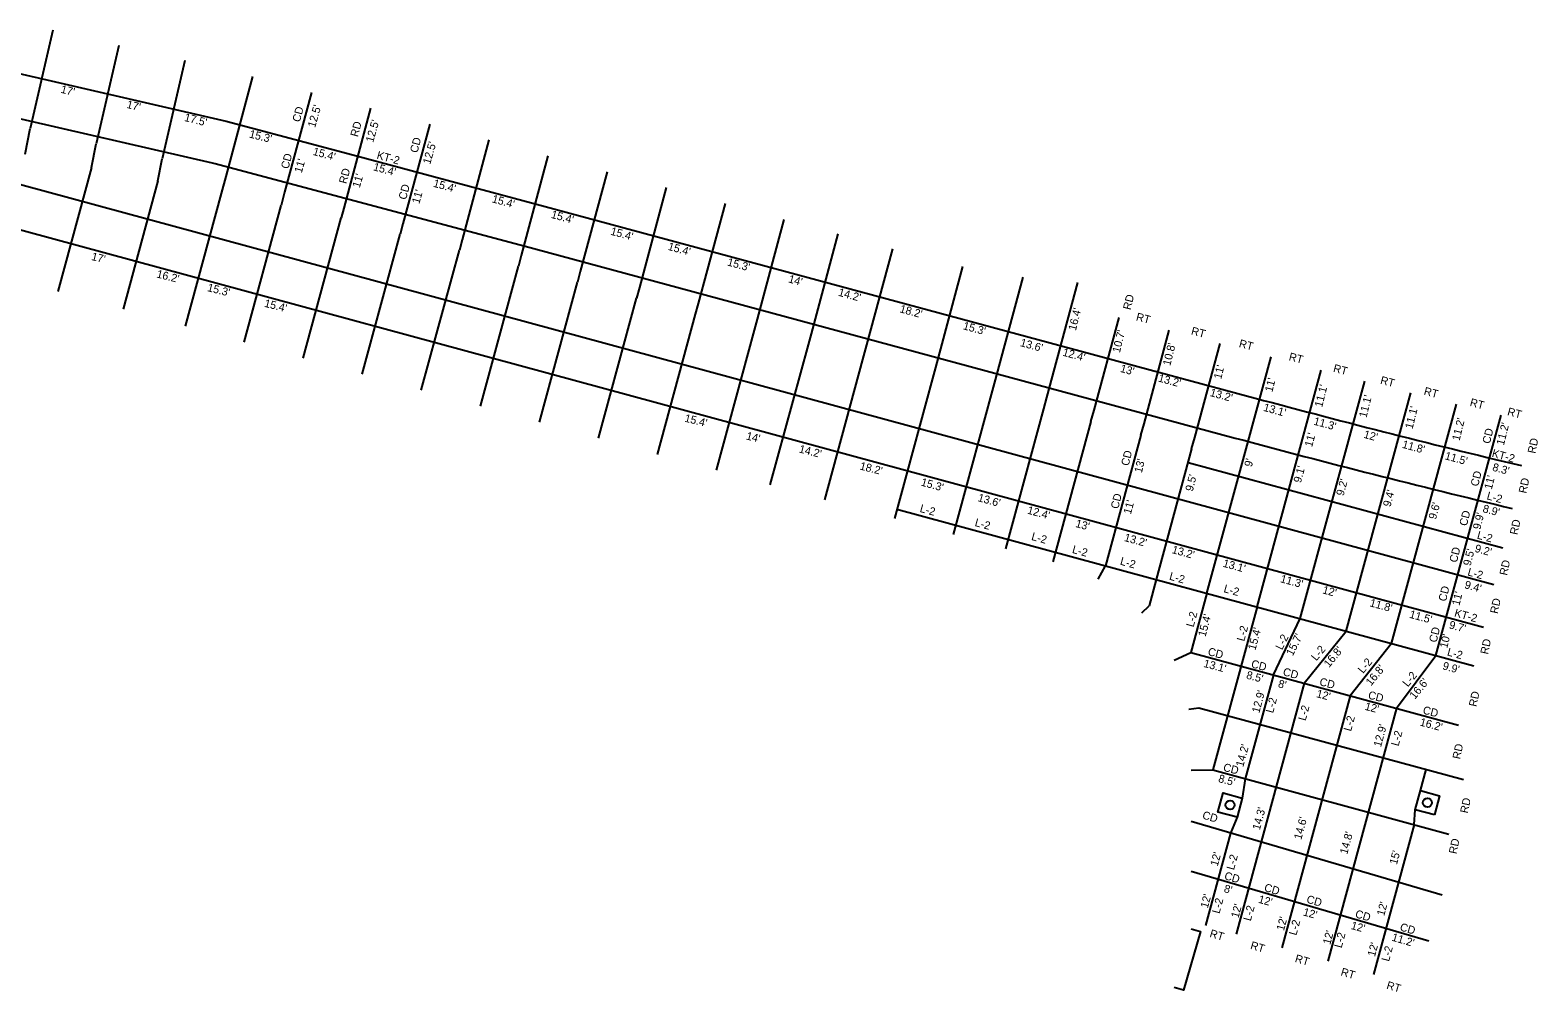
# Model space of a CAD drawing. Extents: x 4995357 to 4999033, y 3881202 to 3881750.
# Drawn here: x 4998653.9 to 4999033, y 3881202.4 to 3881444.2 of the extents above; entities that cross this region are included whole.
import ezdxf

# ---------------------------------------------------------------- set-up
doc = ezdxf.new("R2010")
doc.units = 0
for name, color, linetype in [('dsn3DCenterLine', 7, 'Continuous'), ('dsn3DCurbFormgrade', 7, 'Continuous'), ('dsn3DCurbTop', 7, 'Continuous'), ('dsn3DDitchFront', 7, 'Continuous'), ('dsn3DDNC', 7, 'Continuous'), ('dsn3DExistingPvmtBtm', 7, 'Continuous')]:
    doc.layers.add(name, color=color, linetype=linetype)

msp = doc.modelspace()

# ---------------------------------------------------------------- linework, layer by layer
at = {"layer": 'dsn3DCurbFormgrade'}
for p, q in [((4998659.59, 3881444.17), (4998653.9, 3881419.44)), ((4998676.2, 3881440.35), (4998670.51, 3881415.62)), ((4998692.81, 3881436.53), (4998687.12, 3881411.8)), ((4998709.81, 3881432.48), (4998703.09, 3881407.37)), ((4998724.61, 3881428.52), (4998717.89, 3881403.41)), ((4998739.5, 3881424.54), (4998732.78, 3881399.43)), ((4998754.36, 3881420.57), (4998747.64, 3881395.45)), ((4998769.22, 3881416.59), (4998762.5, 3881391.47)), ((4998784.09, 3881412.61), (4998777.37, 3881387.5)), ((4998669.31, 3881409.65), (4998660.85, 3881378.49)), ((4998799, 3881408.59), (4998792.22, 3881383.49)), ((4998686.01, 3881406.29), (4998677.25, 3881374.03)), ((4998813.85, 3881404.58), (4998807.08, 3881379.48)), ((4998701.95, 3881403.08), (4998692.9, 3881369.78)), ((4998821.94, 3881375.47), (4998828.72, 3881400.57)), ((4998707.68, 3881365.77), (4998717, 3881400.05)), ((4998722.55, 3881361.73), (4998732.12, 3881396.95)), ((4998836.75, 3881371.47), (4998843.52, 3881396.57)), ((4998737.4, 3881357.7), (4998746.96, 3881392.92)), ((4998857.01, 3881392.93), (4998850.24, 3881367.83)), ((4998752.25, 3881353.66), (4998761.81, 3881388.89)), ((4998870.74, 3881389.23), (4998863.96, 3881364.13)), ((4998767.09, 3881349.63), (4998776.66, 3881384.85)), ((4998888.36, 3881384.75), (4998881.52, 3881359.38)), ((4998903.53, 3881382.09), (4998896.3, 3881355.32)), ((4998781.94, 3881345.6), (4998791.51, 3881380.82)), ((4998917.24, 3881380.72), (4998909.45, 3881351.84)), ((4998796.79, 3881341.57), (4998806.35, 3881376.79)), ((4998811.64, 3881337.53), (4998821.2, 3881372.76)), ((4998921.4, 3881348.62), (4998927.7, 3881371.95)), ((4998826.44, 3881333.51), (4998836, 3881368.74)), ((4998933.96, 3881345.22), (4998940.3, 3881368.72)), ((4998849.49, 3881365.08), (4998839.92, 3881329.85)), ((4998946.72, 3881341.78), (4998953.1, 3881365.41)), ((4998863.21, 3881361.35), (4998853.64, 3881326.13)), ((4998960.14, 3881340.74), (4998965.89, 3881362.03)), ((4998962.4, 3881299.18), (4998978.52, 3881358.69)), ((4998880.76, 3881356.58), (4998871.19, 3881321.36)), ((4998973.26, 3881296.23), (4998989.46, 3881355.9)), ((4998895.55, 3881352.57), (4998885.99, 3881317.34)), ((4998984.81, 3881293.09), (4999001.07, 3881352.95)), ((4998908.68, 3881349), (4998899.11, 3881313.78)), ((4998996.21, 3881290), (4999012.55, 3881350.14)), ((4999007.31, 3881286.98), (4999023.72, 3881347.41)), ((4998920.62, 3881345.76), (4998911.06, 3881310.53)), ((4998933.18, 3881342.35), (4998924.27, 3881309.54)), ((4998949.79, 3881302.61), (4998960.14, 3881340.74)), ((4998945.94, 3881338.88), (4998937.03, 3881306.07)), ((4998922.41, 3881306.15), (4998924.27, 3881309.54)), ((4998933.4, 3881297.68), (4998935.22, 3881299.41)), ((4998966.52, 3881282.08), (4998973.26, 3881296.23)), ((4998974.24, 3881279.99), (4998984.81, 3881293.09)), ((4998941.54, 3881285.76), (4998945.75, 3881287.72)), ((4998945.75, 3881287.72), (4999012.99, 3881269.46)), ((4998996.21, 3881290), (4998985.82, 3881276.84)), ((4998997.4, 3881273.7), (4999007.31, 3881286.98)), ((4998945.26, 3881273.46), (4998947.73, 3881273.83)), ((4998947.73, 3881273.83), (4999014.27, 3881255.76)), ((4998945.79, 3881258.17), (4998951.28, 3881258.18)), ((4998951.28, 3881258.18), (4999010.56, 3881242.08)), ((4999008.92, 3881226.7), (4998945.79, 3881245.19)), ((4999005.54, 3881215.18), (4998945.82, 3881232.68))]:
    msp.add_line(p, q, dxfattribs=at)
msp.add_arc((4999585.3, 3883669.29), 2411, 254.89079, 256.59997, dxfattribs=at)
at = {"layer": 'dsn3DCurbTop'}
for p, q in [((4998652.61, 3881413.01), (4998653.9, 3881419.44)), ((4998669.31, 3881409.65), (4998670.51, 3881415.62)), ((4998686.01, 3881406.29), (4998687.12, 3881411.8)), ((4998703.09, 3881407.37), (4998701.95, 3881403.08)), ((4998717.89, 3881403.41), (4998717, 3881400.05)), ((4998732.78, 3881399.43), (4998732.12, 3881396.95)), ((4998747.64, 3881395.45), (4998746.96, 3881392.92)), ((4998762.5, 3881391.47), (4998761.81, 3881388.89)), ((4998777.37, 3881387.5), (4998776.66, 3881384.85)), ((4998792.22, 3881383.49), (4998791.51, 3881380.82)), ((4998807.08, 3881379.48), (4998806.35, 3881376.79)), ((4998821.2, 3881372.76), (4998821.94, 3881375.47)), ((4998836, 3881368.74), (4998836.75, 3881371.47)), ((4998850.24, 3881367.83), (4998849.49, 3881365.08)), ((4998863.96, 3881364.1), (4998863.21, 3881361.35)), ((4998881.5, 3881359.34), (4998880.76, 3881356.58)), ((4998896.3, 3881355.32), (4998895.55, 3881352.57)), ((4998909.45, 3881351.84), (4998908.68, 3881349)), ((4998920.62, 3881345.76), (4998921.4, 3881348.62)), ((4998933.18, 3881342.35), (4998933.96, 3881345.22)), ((4998945.94, 3881338.88), (4998946.72, 3881341.76))]:
    msp.add_line(p, q, dxfattribs=at)
at = {"layer": 'dsn3DDitchFront'}
for p, q in [((4998736.27, 3881412.47), (4998783.36, 3881399.87)), ((4998614.91, 3881403.91), (4999019.28, 3881294.09)), ((4998783.36, 3881399.87), (4998959.72, 3881352.25))]:
    msp.add_line(p, q, dxfattribs=at)
msp.add_arc((4999585.3, 3883669.29), 2400, 254.89079, 256.59429, dxfattribs=at)
at = {"layer": 'dsn3DDNC'}
for p, q in [((4998630.07, 3881438.13), (4998703.22, 3881421.31)), ((4998627.39, 3881427.46), (4998700.75, 3881410.59)), ((4998703.22, 3881421.31), (4998736.27, 3881412.47)), ((4998614.25, 3881415.49), (4999021.9, 3881304.78)), ((4998700.38, 3881410.68), (4998780.52, 3881389.24)), ((4998780.5, 3881389.25), (4998956.85, 3881341.63)), ((4998945.02, 3881335.5), (4999024.16, 3881314.01)), ((4998871.84, 3881323.77), (4999016.9, 3881284.38)), ((4998937.03, 3881306.07), (4998935.22, 3881299.41)), ((4998949.79, 3881302.61), (4998945.75, 3881287.73)), ((4998962.4, 3881299.18), (4998951.28, 3881258.18)), ((4998974.24, 3881279.99), (4998957.1, 3881216.87)), ((4998966.52, 3881282.08), (4998959.43, 3881255.97)), ((4998985.82, 3881276.84), (4998968.62, 3881213.5)), ((4998997.4, 3881273.7), (4998980.14, 3881210.12)), ((4999003.47, 3881253.02), (4999004.9, 3881258.3)), ((4998959.43, 3881255.97), (4998958.67, 3881251.12)), ((4998957.36, 3881246.29), (4998955.71, 3881242.29)), ((4999001.89, 3881244.43), (4999002.16, 3881248.19)), ((4998955.71, 3881242.29), (4998949.42, 3881219.12)), ((4999001.89, 3881244.43), (4998991.66, 3881206.75))]:
    msp.add_line(p, q, dxfattribs=at)
at = {"layer": 'dsn3DExistingPvmtBtm'}
for points in [[(4998957.36, 3881246.29), (4998952.53, 3881247.6), (4998953.84, 3881252.43), (4998958.67, 3881251.12)], [(4999006.98, 3881246.88), (4999002.16, 3881248.19), (4999003.47, 3881253.02), (4999008.29, 3881251.71)]]:
    msp.add_lwpolyline(points, close=True, dxfattribs=at)
msp.add_lwpolyline([(4998945.79, 3881218.24), (4998948.19, 3881217.54), (4998943.9, 3881202.82), (4998941.5, 3881203.52)], dxfattribs=at)
for centre in [(4998955.6, 3881249.36), (4999005.22, 3881249.95)]:
    msp.add_circle(centre, 1.12, dxfattribs=at)

# ---------------------------------------------------------------- texts
at = {"layer": 'dsn3DCenterLine'}
for s, rotation, p in [("17'", 345.9626, (4998661.46, 3881428.46)), ("17'", 345.9626, (4998678.01, 3881424.65)), ("17.5'", 345.9626, (4998692.53, 3881421.36)), ('CD', 75.0269, (4998721.7, 3881420.92)), ("12.5'", 73.8704, (4998725.54, 3881419.53)), ('RD', 75.0269, (4998736.29, 3881417.2)), ("12.5'", 73.8704, (4998740.13, 3881415.8)), ("15.3'", 345.9626, (4998708.84, 3881417.21)), ('CD', 75.0269, (4998751.27, 3881413.18)), ("12.5'", 73.8704, (4998754.48, 3881410.31)), ('CD', 75.0269, (4998718.83, 3881409.14)), ("11'", 73.8704, (4998722.17, 3881408.12)), ("15.4'", 344.7365, (4998724.84, 3881412.84)), ('KT-2', 344.7365, (4998740.9, 3881411.89)), ('RD', 75.0269, (4998733.42, 3881405.41)), ("11'", 73.8704, (4998736.76, 3881404.39)), ("15.4'", 344.7365, (4998740.02, 3881408.98)), ('CD', 75.0269, (4998748.4, 3881401.4)), ("11'", 73.8704, (4998751.74, 3881400.38)), ("15.4'", 344.7365, (4998755.1, 3881404.83)), ("15.4'", 344.7365, (4998769.88, 3881400.91)), ("15.4'", 344.7365, (4998784.73, 3881397)), ("15.4'", 344.7365, (4998799.68, 3881392.78)), ("15.4'", 344.7365, (4998814.11, 3881388.96)), ("17'", 345.9626, (4998669.16, 3881386.41)), ("15.3'", 344.7365, (4998829.04, 3881385.04)), ("16.2'", 345.9626, (4998685.54, 3881382.02)), ("14'", 344.7365, (4998844.4, 3881380.79)), ("15.3'", 345.9626, (4998698.31, 3881378.59)), ("14.2'", 344.7365, (4998856.94, 3881377.43)), ('RD', 75.9626, (4998930.57, 3881373.71)), ("15.4'", 345.9626, (4998712.63, 3881374.65)), ("18.2'", 344.7365, (4998872.39, 3881373.27)), ("16.4'", 75.9626, (4998916.82, 3881368.49)), ("15.3'", 344.7365, (4998888.31, 3881369)), ('RT', 345.4164, (4998931.82, 3881371.24)), ("13.6'", 344.7365, (4998902.68, 3881364.77)), ("10.7'", 75.9626, (4998927.88, 3881362.92)), ('RT', 345.4164, (4998945.67, 3881367.69)), ('RT', 345.4164, (4998957.69, 3881364.54)), ("12.4'", 344.7365, (4998913.35, 3881362.37)), ("10.8'", 75.9626, (4998940.56, 3881359.67)), ('RT', 345.4164, (4998970.23, 3881361.22)), ("13'", 344.7365, (4998927.83, 3881358.29)), ("11'", 75.9626, (4998953.36, 3881356.3)), ('RT', 345.4164, (4998981.39, 3881358.31)), ("13.2'", 344.7365, (4998937.38, 3881355.88)), ("11'", 75.9626, (4998966.23, 3881353.05)), ("11.1'", 75.9626, (4998978.74, 3881349.23)), ('RT', 345.4164, (4998993.23, 3881355.3)), ("13.2'", 344.7365, (4998950.39, 3881352.22)), ("11.1'", 75.9626, (4998989.89, 3881346.6)), ('RT', 345.4164, (4999004.18, 3881352.56)), ('RT', 345.4164, (4999015.75, 3881349.73)), ("15.4'", 345.9626, (4998818.3, 3881345.78)), ("13.1'", 344.7365, (4998963.83, 3881348.49)), ("11.1'", 75.9626, (4999001.47, 3881343.76)), ('RT', 345.4164, (4999025.17, 3881347.42)), ("11.3'", 344.7365, (4998976.45, 3881345.03)), ("12'", 344.7365, (4998989.04, 3881341.72)), ("11.2'", 75.9626, (4999013.28, 3881340.81)), ('CD', 75.9626, (4999020.91, 3881340.05)), ("11.2'", 75.9626, (4999024.44, 3881339.66)), ("14'", 345.9626, (4998833.78, 3881341.3)), ("14.2'", 345.9626, (4998847.06, 3881338.02)), ("11'", 74.8061, (4998976.21, 3881339.24)), ("11.8'", 344.7365, (4998998.72, 3881339.21)), ('RD', 77.9434, (4999032.33, 3881337.61)), ('CD', 75.9626, (4998930.08, 3881334.49)), ("13'", 75.9626, (4998933.4, 3881332.72)), ("9'", 74.8061, (4998961.03, 3881334.21)), ("11.5'", 344.7365, (4999009.46, 3881336.32)), ('KT-2', 344.7365, (4999021.28, 3881336.95)), ("18.2'", 345.9626, (4998862.36, 3881333.74)), ("9.5'", 75.9626, (4998946.22, 3881328.08)), ("9.1'", 74.8061, (4998973.4, 3881330.22)), ('CD', 75.9626, (4999017.96, 3881329.33)), ("11'", 75.9626, (4999021.38, 3881328.56)), ("8.3'", 344.7365, (4999021.41, 3881333.46)), ("15.3'", 344.7365, (4998877.73, 3881329.7)), ("9.2'", 74.8061, (4998984.13, 3881326.95)), ("9.4'", 74.8061, (4998995.91, 3881324.19)), ('RD', 77.9434, (4999030.07, 3881327.59)), ('L-2', 344.7349, (4998877.45, 3881323.08)), ("13.6'", 344.7365, (4998892.03, 3881325.79)), ("12.4'", 344.7365, (4998904.46, 3881322.66)), ('CD', 75.9626, (4998927.47, 3881323.67)), ("11'", 74.8061, (4998930.65, 3881322.33)), ("9.6'", 74.8061, (4999007.36, 3881321.03)), ("8.9'", 344.7365, (4999018.97, 3881323.04)), ('L-2', 344.7349, (4999019.99, 3881326.26)), ('L-2', 344.7349, (4998891.27, 3881319.55)), ("13'", 344.7365, (4998916.59, 3881319.3)), ('CD', 75.9626, (4999015.12, 3881319.38)), ("9.9'", 75.9626, (4999018.52, 3881318.48)), ('RD', 77.9434, (4999027.85, 3881317.17)), ('L-2', 344.7349, (4998905.49, 3881316.04)), ("13.2'", 344.7365, (4998928.83, 3881315.77)), ('L-2', 344.7349, (4999017.55, 3881316.38)), ('L-2', 344.7349, (4998915.75, 3881312.78)), ("13.2'", 344.7365, (4998940.82, 3881312.73)), ('CD', 75.9626, (4999012.61, 3881310.19)), ("9.5'", 75.9626, (4999016.08, 3881309.36)), ("9.2'", 344.7365, (4999016.98, 3881313.04)), ('L-2', 344.7349, (4998927.81, 3881309.83)), ("13.1'", 344.7365, (4998953.65, 3881309.3)), ('RD', 77.9434, (4999025.24, 3881306.96)), ('L-2', 344.7349, (4998940.17, 3881306.05)), ("11.3'", 344.7365, (4998968.09, 3881305.41)), ("9.4'", 344.7365, (4999014.41, 3881303.91)), ('L-2', 344.7349, (4999015.17, 3881307.13)), ('L-2', 344.7349, (4998953.84, 3881302.91)), ("12'", 344.7365, (4998978.69, 3881302.61)), ('CD', 75.9626, (4999009.87, 3881300.41)), ("11'", 75.9626, (4999013.25, 3881299.37)), ('L-2', 74.8061, (4998946.41, 3881293.96)), ("11.8'", 344.7365, (4998990.56, 3881299.36)), ("11.5'", 344.7365, (4999000.54, 3881296.48)), ('KT-2', 344.4604, (4999011.84, 3881296.82)), ('RD', 77.9434, (4999022.88, 3881297.34)), ("15.4'", 74.8061, (4998949.41, 3881291.53)), ('L-2', 74.8061, (4998959.15, 3881290.4)), ("15.4'", 74.8061, (4998961.96, 3881288.15)), ('CD', 75.9626, (4999007.5, 3881290.09)), ("9.7'", 344.7365, (4999010.5, 3881293.82)), ('L-2', 63.6883, (4998968.67, 3881288.2)), ("15.7'", 63.6883, (4998971.36, 3881286.7)), ("10'", 75.9626, (4999010.18, 3881288.66)), ('RD', 77.9434, (4999020.44, 3881287.13)), ('CD', 345.1995, (4998949.86, 3881287.09)), ('L-2', 50.4873, (4998977.28, 3881285.46)), ("16.8'", 50.4873, (4998980.47, 3881283.78)), ('L-2', 344.7349, (4999010.04, 3881287.01)), ("13.1'", 345.1995, (4998948.79, 3881284.12)), ("8.5'", 345.1995, (4998959.53, 3881281.19)), ('CD', 345.1995, (4998960.75, 3881284.01)), ('CD', 345.1995, (4998968.74, 3881282.01)), ('L-2', 50.6731, (4998989.05, 3881282.29)), ("16.8'", 50.6731, (4998991.03, 3881279.17)), ('L-2', 50.6731, (4999000.29, 3881278.91)), ("9.9'", 344.7365, (4999008.88, 3881283.51)), ("8'", 345.1995, (4998967.53, 3881279.01)), ('CD', 345.1995, (4998977.92, 3881279.51)), ("16.6'", 50.6731, (4999002.05, 3881275.8)), ("12.9'", 74.8061, (4998962.94, 3881272.35)), ('L-2', 74.8061, (4998966.41, 3881272.34)), ("12'", 345.1995, (4998977.16, 3881276.51)), ('CD', 345.1995, (4998990.15, 3881276.17)), ('RD', 77.9434, (4999017.54, 3881273.96)), ('L-2', 74.8061, (4998974.58, 3881270.41)), ('L-2', 74.8061, (4998986.01, 3881267.77)), ("12'", 345.1995, (4998989.33, 3881273.34)), ('CD', 345.1995, (4999003.91, 3881272.38)), ("12.9'", 74.8061, (4998993.54, 3881263.82)), ('L-2', 74.8061, (4998997.95, 3881264.04)), ("16.2'", 345.1995, (4999003.17, 3881269.38)), ("14.2'", 74.8061, (4998958.9, 3881258.81)), ('RD', 77.9434, (4999013.43, 3881260.77)), ("8.5'", 345.1995, (4998952.5, 3881255.18)), ('CD', 345.1995, (4998953.72, 3881258)), ("14.3'", 74.8061, (4998963.07, 3881242.94)), ('RD', 77.9434, (4999015.35, 3881247.17)), ('CD', 343.6703, (4998948.46, 3881246)), ("14.6'", 74.8061, (4998973.51, 3881240.53)), ("14.8'", 74.8061, (4998985.05, 3881236.84)), ("12'", 74.8061, (4998952.48, 3881233.84)), ("15'", 74.8061, (4998997.53, 3881234.24)), ('RD', 77.9434, (4999012.51, 3881236.94)), ('L-2', 74.8061, (4998956.57, 3881232.9)), ('CD', 343.6703, (4998953.99, 3881230.75)), ("12'", 74.8061, (4998949.99, 3881223.29)), ('L-2', 74.8061, (4998952.92, 3881221.93)), ("8'", 344.7365, (4998953.9, 3881227.49)), ("12'", 344.7365, (4998962.55, 3881224.83)), ('CD', 343.6703, (4998964.02, 3881227.78)), ('CD', 343.6703, (4998974.66, 3881224.86)), ("12'", 74.8061, (4998957.7, 3881220.82)), ('L-2', 74.8061, (4998960.79, 3881220.07)), ("12'", 344.7365, (4998973.82, 3881221.64)), ('CD', 343.6703, (4998986.9, 3881221.17)), ("12'", 74.8061, (4998994.34, 3881221.36)), ("12'", 74.8061, (4998969.12, 3881217.61)), ('L-2', 74.8061, (4998972.26, 3881216.46)), ("12'", 344.7365, (4998985.85, 3881218.23)), ('CD', 343.6703, (4998998.14, 3881217.86)), ('RT', 343.651, (4998950.32, 3881216.24)), ('RT', 343.651, (4998960.55, 3881213.24)), ("12'", 74.8061, (4998980.79, 3881214.14)), ('L-2', 74.8061, (4998983.63, 3881213.29)), ("12'", 74.8061, (4998992.01, 3881211.12)), ("11.2'", 343.6703, (4998996.1, 3881215.31)), ('RT', 343.651, (4998971.76, 3881209.95)), ('L-2', 74.8061, (4998995.55, 3881209.9)), ('RT', 343.651, (4998983.28, 3881206.58)), ('RT', 343.651, (4998994.78, 3881203.21))]:
    msp.add_text(s, height=2, rotation=rotation, dxfattribs=at).set_placement(p)

doc.saveas('drawing.dxf')
